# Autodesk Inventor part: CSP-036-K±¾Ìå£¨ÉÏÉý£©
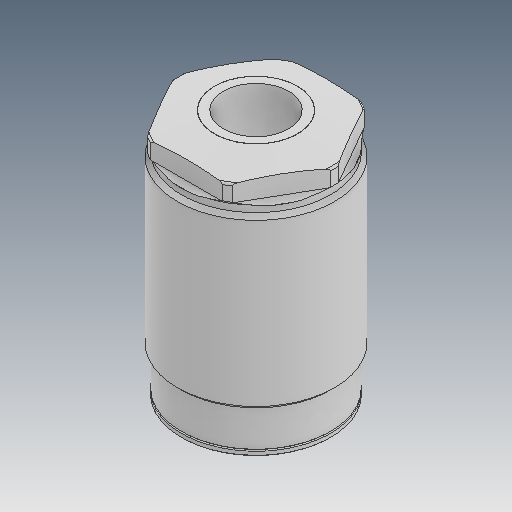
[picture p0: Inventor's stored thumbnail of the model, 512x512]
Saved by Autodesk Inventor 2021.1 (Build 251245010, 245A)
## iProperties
Created: 2019-01
Part Number: CSP-036-K±¾Ìå£¨ÉÏÉý£©
Material: Ogólny
Document SubType Name: Modeling
Designer: user
Density: 1 g/cm^3
Appearance: Domyślna
Author: user
Revision Number: ÈÎºÎ
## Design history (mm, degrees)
feature "ÇÐ³ý-À­Éì2"
node "Bryła1"
